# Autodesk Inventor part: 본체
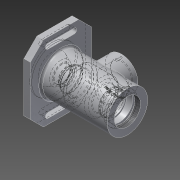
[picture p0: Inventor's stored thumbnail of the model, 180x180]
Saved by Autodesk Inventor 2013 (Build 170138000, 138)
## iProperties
Created: 2017-10
Part Number: 본체
Material: 알루미늄 6061
Document SubType Name: Modeling
Designer: Administrator
Density: 2.71 g/cm^3
Mass: 740.593 g
Surface Area: 658.234 cm^2
Volume: 273.281 cm^3
Author: Administrator
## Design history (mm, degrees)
sketch "스케치1"
  geometry: L1 (44.5, 35)-(57.5, 35); L2 (-57.5, 31)-(44.5, 31); L3 (44.5, 31)-(44.5, 35); L4 (57.5, 35)-(57.5, 0); L5 (57.5, 0)-(-57.5, 0); L6 (-57.5, 0)-(-57.5, 31); 2 further points
  constraints: 12 end point, 3 horizontal, 3 vertical, 2 coincident, 1 midpoint
  dimensions: "d0" = 35 distance from line of point (0, 0) L1; "d1" = 31 distance from line of point (0, 0) L2; "d2" = 115 distance between parallel lines of L6 L4; "d3" = 13 distance between parallel lines of L4 L3
revolve "회전1" sketch "스케치1" stored, may be unused: angle "d4" = 90 deg
sketch "스케치2"
  geometry: L1 (-58, 47)-(58, 47); L2 (58, 47)-(58, -47); L3 (58, -47)-(-58, -47); L4 (-58, -47)-(-58, 47); C1 r 35 at (0, 0) reference; 2 further points
  constraints: 8 end point, 2 midpoint, 2 parallel, 1 horizontal, 1 horizontal alignment, 1 perpendicular, 1 vertical alignment
  dimensions: "d5" = 116 distance of L2.end L3.end; "d7" = 94 distance of L1.end L2.end
extrude "돌출1" join sketch "스케치2" distance "d8" = 10; taper "d9" = 0 deg
chamfer "모따기1" distance "d10" = 20; stored, may be unused: second distance "d11" = 2, angle "d12" = 45 deg
sketch "스케치3"
  geometry: L1 (42, 24)-(50, 24); L2 (50, 24)-(50, -24); L3 (50, -24)-(42, -24); L4 (42, -24)-(42, 24); L5 (-50, -24)-(-42, -24); L6 (-42, -24)-(-42, 24); L7 (-42, 24)-(-50, 24); L8 (-50, 24)-(-50, -24); C1 r 35 at (0, 0) reference
  constraints: 16 end point, 4 parallel, 2 horizontal, 2 perpendicular
  dimensions: "d13" = 48 distance of L1.end L2.end; "d15" = 48 distance of L7.end L5.start; "d16" = 24 distance from line of C1.centre L1; "d17" = 24 distance from line of C1.centre L7; "d18" = 8 distance of L6.end L7.end; "d19" = 8 distance of L1.start L1.end; "d21" = 84 distance between parallel lines of L6 L4; "d22" = 42 distance from line of C1.centre L6
extrude "돌출2" cut sketch "스케치3" distance "d23" = 10; taper "d24" = 0 deg
fillet "모깎기1" dims "d25" = 4
sketch "스케치4"
  geometry: L1 (44.5, -50)-(54.5, -50) reference; L2 (54.5, -50)-(54.5, -58) reference; L3 (54.5, -58)-(44.5, -58) reference; L4 (44.5, -58)-(44.5, -50) reference; L5 (54.5, 50)-(44.5, 50) reference; L6 (44.5, 50)-(44.5, 58) reference; L7 (44.5, 58)-(54.5, 58) reference; L8 (54.5, 58)-(54.5, 50) reference; L9 (-57.5, -31)-(-57.5, 31) reference; L10 (-57.5, 31)-(44.5, 31) reference; L11 (44.5, 31)-(44.5, 42) reference; L12 (44.5, 42)-(54.5, 42) reference; L13 (54.5, 42)-(54.5, 35) reference; L14 (54.5, 35)-(57.5, 35) reference; L15 (57.5, 35)-(57.5, -35) reference; L16 (57.5, -35)-(54.5, -35) reference; L17 (54.5, -35)-(54.5, -42) reference; L18 (54.5, -42)-(44.5, -42) reference; L19 (44.5, -42)-(44.5, -31) reference; L20 (44.5, -31)-(-57.5, -31) reference; L21 (-31.5, 0)-(-57.5, 0); L22 (-57.5, -31)-(-57.5, 31) reference; L23 (-57.5, 21)-(-48.5, 21); L24 (-48.5, 21)-(-48.5, 24); L25 (-48.5, 24)-(-45.5, 24); L26 (-45.5, 24)-(-45.5, 20); L27 (-45.5, 20)-(-36.5, 20); L28 (-36.5, 20)-(-36.5, 17.5); L29 (-36.5, 17.5)-(-33.25, 17.5); L30 (-33.25, 18.5)-(-31.5, 18.5); L31 (-31.5, 18.5)-(-31.5, 0); L32 (-33.25, 17.5)-(-33.25, 18.5); 1 further point
  constraints: 22 end point, 4 horizontal, 4 vertical, 1 midpoint, 1 perpendicular, 1 point on line
  dimensions: "d26" = 21 distance between parallel lines of L21 L23; "d28" = 9 distance of L23.start L23.end; "d29" = 3 distance of L24.end L25.end; "d30" = 24 distance between parallel lines of L21 L25; "d31" = 12 distance between parallel lines of L9 L26; "d32" = 20 distance between parallel lines of L21 L27; "d33" = 21 distance between parallel lines of L9 L28; "d34" = 17.5 distance between parallel lines of L21 L29; "d37" = 18.5 distance between parallel lines of L21 L30; "d127" = 5 distance between parallel lines of L31 L28; "d128" = 1.75 distance of L30.start L30.end
revolve "회전2" sketch "스케치4" stored, may be unused: angle "d38" = 90 deg
sketch "스케치5"
  geometry: C1 r 18.5 at (0, 0) reference; C2 r 17.5 at (0, 0)
  constraints: 1 centre point, 1 coincident
  dimensions: "d39" = 35 diameter of C2
extrude "돌출3" cut sketch "스케치5" distance "d41" = 60; taper "d42" = 0 deg
node "작업 평면1"
sketch "스케치6"
  geometry: C1 r 26 at (0, 0); 1 further point
  constraints: 1 centre point, 1 coincident
  dimensions: "d44" = 52 diameter of C1
extrude "돌출4" cut sketch "스케치6" stored distance "d46" = 38; taper "d47" = 0 deg
fillet "모깎기2" dims "d53" = 3
sketch "스케치8"
  geometry: C1 r 16.5 at (0, 0); C2 r 17.5 at (0, 0) reference; 1 further point
  constraints: 3 coincident, 1 centre point
  dimensions: "d54" = 33 diameter of C1
extrude "돌출5" cut sketch "스케치8" distance "d56" = 5; taper "d57" = 0 deg
fillet "모깎기4" dims "d59" = 3
sketch "스케치9"
  geometry: L1 (44.5, -50)-(54.5, -50) reference; L2 (54.5, -50)-(54.5, -58) reference; L3 (54.5, -58)-(44.5, -58) reference; L4 (44.5, -58)-(44.5, -50) reference; L5 (54.5, 50)-(44.5, 50) reference; L6 (44.5, 50)-(44.5, 58) reference; L7 (44.5, 58)-(54.5, 58) reference; L8 (54.5, 58)-(54.5, 50) reference; L9 (57.5, 35)-(57.5, -35) reference; L10 (57.5, -35)-(54.5, -35) reference; L11 (54.5, -35)-(54.5, -42) reference; L12 (54.5, -42)-(44.5, -42) reference; L13 (44.5, -42)-(44.5, -31) reference; L14 (44.5, -31)-(-57.5, -31) reference; L15 (-57.5, -31)-(-57.5, -21) reference; L16 (-57.5, -21)-(-48.5, -21) reference; L17 (-48.5, -21)-(-48.5, -24) reference; L18 (-48.5, -24)-(-45.5, -24) reference; L19 (-45.5, -24)-(-45.5, -20) reference; L20 (-45.5, -20)-(-36.5, -20) reference; L21 (-36.5, -20)-(-36.5, -17.5) reference; L22 (-36.5, -17.5)-(-33.25, -17.5) reference; L23 (-33.25, -17.5)-(-33.25, -18.5) reference; L24 (-33.25, -18.5)-(-31.5, -18.5) reference; L25 (-20.5, -17.5)-(-20.5, -23) reference; L26 (-17.5, -26)-(14.5, -26) reference; L27 (17.5, -23)-(17.5, -17.5) reference; L28 (28.5, -17.5)-(28.5, -16.5) reference; L29 (28.5, -16.5)-(30.5, -16.5) reference; L30 (33.5, -13.5)-(33.5, 13.5) reference; L31 (30.5, 16.5)-(28.5, 16.5) reference; L32 (28.5, 16.5)-(28.5, 17.5) reference; L33 (17.5, 17.5)-(17.5, 23) reference; L34 (14.5, 26)-(-17.5, 26) reference; L35 (-20.5, 23)-(-20.5, 17.5) reference; L36 (-31.5, 18.5)-(-33.25, 18.5) reference; L37 (-33.25, 18.5)-(-33.25, 17.5) reference; L38 (-33.25, 17.5)-(-36.5, 17.5) reference; L39 (-36.5, 17.5)-(-36.5, 20) reference; L40 (-36.5, 20)-(-45.5, 20) reference; L41 (-45.5, 20)-(-45.5, 24) reference; L42 (-45.5, 24)-(-48.5, 24) reference; L43 (-48.5, 24)-(-48.5, 21) reference; L44 (-48.5, 21)-(-57.5, 21) reference; L45 (-57.5, 21)-(-57.5, 31) reference; L46 (-57.5, 31)-(44.5, 31) reference; L47 (44.5, 31)-(44.5, 42) reference; L48 (44.5, 42)-(54.5, 42) reference; L49 (54.5, 42)-(54.5, 35) reference; L50 (54.5, 35)-(57.5, 35) reference; L51 (33.5, 10)-(36.2, 10); L52 (36.2, 10)-(36.2, 12.2); L53 (36.5, 12.5)-(42.8, 12.5); L54 (43.5, 12.904)-(43.5, 14.022); L55 (42.8, 12.5)-(43.5, 12.904); L56 (57.5, -35)-(57.5, 35) reference; L57 (45.318, 16.779)-(57.5, 22); L58 (57.5, 0)-(33.5, 0); L59 (33.5, -13.5)-(33.5, 13.5) reference; L60 (33.5, 0)-(33.5, 10); L61 (57.5, 0)-(57.5, 22); L62 (-31.5, -18.5)-(-31.5, -17.5) reference; L63 (-31.5, -17.5)-(-20.5, -17.5) reference; L64 (17.5, -17.5)-(28.5, -17.5) reference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; A1 r 3 centre (-17.5, -23) between (-20.5, -23) and (-17.5, -26) reference; A2 r 3 centre (14.5, -23) between (14.5, -26) and (17.5, -23) reference; A3 r 3 centre (30.5, -13.5) between (30.5, -16.5) and (33.5, -13.5) reference; A4 r 3 centre (30.5, 13.5) between (33.5, 13.5) and (30.5, 16.5) reference; A5 r 3 centre (14.5, 23) between (17.5, 23) and (14.5, 26) reference; A6 r 3 centre (-17.5, 23) between (-17.5, 26) and (-20.5, 23) reference; A7 r 0.3 centre (36.5, 12.2) between (36.5, 12.5) and (36.2, 12.2); A8 r 3 centre (46.5, 14.022) between (45.318, 16.779) and (43.5, 14.022); 2 further points
  constraints: 18 end point, 4 point on circle, 4 point on line, 4 tangent, 4 vertical, 2 centre point, 2 midpoint, 1 horizontal, 1 perpendicular
  dimensions: "d60" = 2.7 distance of L51.start L51.end; "d62" = 10 distance from line of point (0, 0) L51; "d63" = 12.5 distance from line of point (0, 0) L53; "d64" = 0.3 radius of A7; "d65" = 7.3 distance between parallel lines of L52 L54; "d68" = 30 deg angle of L53 L55; "d69" = 0.7 horizontal distance of L54.start L53.end; "d72" = 16 vertical distance of point (0, 0) point (43.5, 16); "d73" = 22 vertical distance of point (0, 0) L57.end; "d74" = 3 radius of A8
revolve "회전3" sketch "스케치9" stored, may be unused: angle "d75" = 90 deg
feature "스레드1" dims "d76" = 10, "d77" = 0
sketch "스케치10"
  geometry: L1 (-57.5, -31)-(-57.5, 31) reference; C1 r 25 at (-1.5, 0); 1 further point
  constraints: 1 centre point, 1 horizontal alignment
  dimensions: "d78" = 56 distance from line of L1 C1.centre; "d79" = 50 diameter of C1
extrude "돌출6" join sketch "스케치10" distance "d80" = 47; taper "d81" = 0 deg
sketch "스케치11"
  geometry: C1 r 25 at (0, 0) reference; C2 r 16 at (0, 0); 1 further point
  constraints: 1 centre point, 1 coincident
  dimensions: "d82" = 32 diameter of C2
extrude "돌출7" cut sketch "스케치11" distance "d84" = 47; taper "d85" = 0 deg
chamfer "모따기3" distance "d86" = 1; stored, may be unused: second distance "d87" = 2, angle "d88" = 45 deg
sketch "스케치12"
  geometry: C1 r 25 at (0, 0) reference; 2 further points
  constraints: 1 vertical alignment
  dimensions: "d89" = 20.5 distance of C1.centre point (0, 20.5)
hole "구멍1" sketch "스케치12" at (0, 20.5) diameter "d90" = 2.459; stored, may be unused: countersink angle "d94" = 90 deg, drill point angle "d96" = 118 deg; dims "d91" = 6, "d92" = 4, "d93" = 2, "d95" = 8
node "작업 평면3"
sketch "스케치14"
  geometry: L1 (-56, -31)-(-56, 31) reference; L2 (25, 47)-(-25, 47) reference; 2 further points
  constraints: 1 other
  dimensions: "d101" = 56 distance from line of L1 point (0, 37); "d102" = 10 distance from line of L2 point (0, 37)
feature "엠보싱1" sketch "스케치14" dims "d103" = 0.5, "d104" = 0
sketch "스케치15"
  geometry: L1 (26.5, 17.5)-(26.5, 0) reference; L2 (26.5, 0)-(17.5, 0) reference; L3 (17.5, 0)-(17.5, 46) reference; L4 (17.5, 46)-(18.5, 47) reference; L5 (18.5, 47)-(26.5, 47) reference; L6 (26.5, 47)-(26.5, 31) reference; L7 (26.5, 31)-(57.5, 31) reference; L8 (57.5, 31)-(57.5, 21) reference; L9 (57.5, 21)-(48.5, 21) reference; L10 (48.5, 21)-(48.5, 24) reference; L11 (48.5, 24)-(45.5, 24) reference; L12 (45.5, 24)-(45.5, 20) reference; L13 (45.5, 20)-(36.5, 20) reference; L14 (36.5, 20)-(36.5, 17.5) reference; L15 (36.5, 17.5)-(33.25, 17.5) reference; L16 (33.25, 17.5)-(33.25, 18.5) reference; L17 (33.25, 18.5)-(31.5, 18.5) reference; L18 (-54.5, -47)-(-54.5, -35) reference; L19 (-54.5, -35)-(-57.5, -35) reference; L20 (-57.5, -35)-(-57.5, -22) reference; L21 (-57.5, -22)-(-45.318, -16.779) reference; L22 (-43.5, -14.022)-(-43.5, -12.904) reference; L23 (-43.5, -12.904)-(-42.8, -12.5) reference; L24 (-42.8, -12.5)-(-36.5, -12.5) reference; L25 (-36.2, -12.2)-(-36.2, -10) reference; L26 (-36.2, -10)-(-33.5, -10) reference; L27 (-33.5, -10)-(-33.5, -13.5) reference; L28 (-30.5, -16.5)-(-28.5, -16.5) reference; L29 (-28.5, -16.5)-(-28.5, -17.5) reference; L30 (-17.5, -17.5)-(-17.5, -23) reference; L31 (-14.5, -26)-(17.5, -26) reference; L32 (20.5, -23)-(20.5, -17.5) reference; L33 (31.5, -18.5)-(33.25, -18.5) reference; L34 (33.25, -18.5)-(33.25, -17.5) reference; L35 (33.25, -17.5)-(36.5, -17.5) reference; L36 (36.5, -17.5)-(36.5, -20) reference; L37 (36.5, -20)-(45.5, -20) reference; L38 (45.5, -20)-(45.5, -24) reference; L39 (45.5, -24)-(48.5, -24) reference; L40 (48.5, -24)-(48.5, -21) reference; L41 (48.5, -21)-(57.5, -21) reference; L42 (57.5, -21)-(57.5, -31) reference; L43 (57.5, -31)-(-44.5, -31) reference; L44 (-44.5, -31)-(-44.5, -47) reference; L45 (-44.5, -47)-(-54.5, -47) reference; L46 (-54.5, 35)-(-54.5, 47) reference; L47 (-54.5, 47)-(-44.5, 47) reference; L48 (-44.5, 47)-(-44.5, 31) reference; L49 (-44.5, 31)-(-23.5, 31) reference; L50 (-23.5, 31)-(-23.5, 47) reference; L51 (-23.5, 47)-(-15.5, 47) reference; L52 (-15.5, 47)-(-14.5, 46) reference; L53 (-14.5, 46)-(-14.5, 0) reference; L54 (-14.5, 0)-(-23.5, 0) reference; L55 (-23.5, 0)-(-23.5, 17.5) reference; L56 (-28.5, 17.5)-(-28.5, 16.5) reference; L57 (-28.5, 16.5)-(-30.5, 16.5) reference; L58 (-33.5, 13.5)-(-33.5, 10) reference; L59 (-33.5, 10)-(-36.2, 10) reference; L60 (-36.2, 10)-(-36.2, 12.2) reference; L61 (-36.5, 12.5)-(-42.8, 12.5) reference; L62 (-42.8, 12.5)-(-43.5, 12.904) reference; L63 (-43.5, 12.904)-(-43.5, 14.022) reference; L64 (-45.318, 16.779)-(-57.5, 22) reference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; A1 r 3 centre (-46.5, -14.022) between (-45.318, -16.779) and (-43.5, -14.022) reference; A2 r 0.3 centre (-36.5, -12.2) between (-36.5, -12.5) and (-36.2, -12.2) reference; A3 r 3 centre (-30.5, -13.5) between (-33.5, -13.5) and (-30.5, -16.5) reference; A4 r 3 centre (-14.5, -23) between (-17.5, -23) and (-14.5, -26) reference; A5 r 3 centre (17.5, -23) between (17.5, -26) and (20.5, -23) reference; A6 r 3 centre (-30.5, 13.5) between (-30.5, 16.5) and (-33.5, 13.5) reference; A7 r 0.3 centre (-36.5, 12.2) between (-36.2, 12.2) and (-36.5, 12.5) reference; A8 r 3 centre (-46.5, 14.022) between (-43.5, 14.022) and (-45.318, 16.779) reference; A9 r 3 centre (-14.5, -23) between (-17.5, -23) and (-14.5, -26) reference; A10 r 3 centre (17.5, -23) between (17.5, -26) and (20.5, -23) reference; A11 r 3 centre (-46.5, -14.022) between (-45.318, -16.779) and (-43.5, -14.022) reference; A12 r 0.3 centre (-36.5, -12.2) between (-36.5, -12.5) and (-36.2, -12.2) reference; A13 r 3 centre (-30.5, -13.5) between (-33.5, -13.5) and (-30.5, -16.5) reference; A14 r 3 centre (-30.5, 13.5) between (-30.5, 16.5) and (-33.5, 13.5) reference; A15 r 0.3 centre (-36.5, 12.2) between (-36.2, 12.2) and (-36.5, 12.5) reference; A16 r 3 centre (-46.5, 14.022) between (-43.5, 14.022) and (-45.318, 16.779) reference; 2 further points
  constraints: 2 end point, 2 midpoint, 1 horizontal, 1 horizontal alignment, 1 point on line
revolve "회전4" sketch "스케치15" stored, may be unused: angle "d105" = 90 deg
sketch "스케치16"
  geometry: C1 r 21 at (0, 0) reference; C2 r 31 at (0, 0) reference; C3 r 21 at (0, 0)
  constraints: 1 centre point, 1 coincident
  dimensions: "d106" = 42 diameter of C3
extrude "돌출8" join sketch "스케치16" distance "d108" = 9; taper "d109" = 0 deg
hole "구멍2" diameter "d112" = 40.376; stored, may be unused: countersink angle "d116" = 90 deg, drill point angle "d118" = 118 deg; dims "d113" = 9, "d114" = 4, "d115" = 2, "d117" = 9, "d121" = 10, "d122" = 10
chamfer "모따기4" distance "d119" = 1; stored, may be unused: second distance "d120" = 2, angle "d123" = 45 deg
fillet "모깎기5" dims "d124" = 3
fillet "모깎기6" dims "d125" = 3
fillet "모깎기7" dims "d126" = 0.3
node "솔리드1"
pattern_circular "원형 패턴1" dims angle "d98" = 360 deg
node "절단 모서리 투영1"
node "절단 모서리 투영2"
node "절단 모서리 투영3"
node "절단 모서리 투영4"
other parameters: "d43" = -56
